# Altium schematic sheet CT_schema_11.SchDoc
size 274 x 160 mm
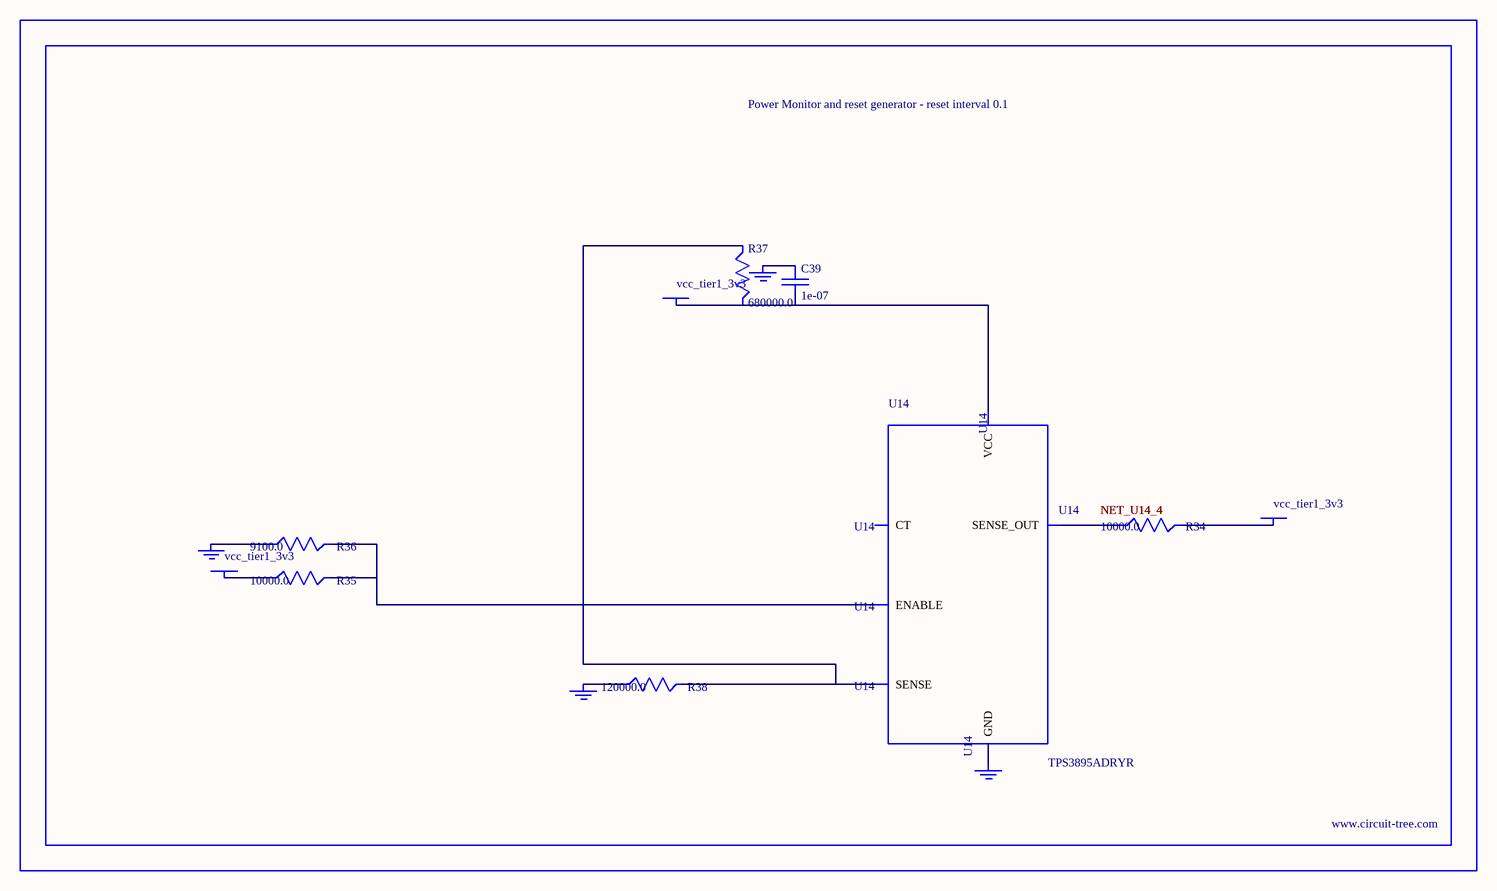
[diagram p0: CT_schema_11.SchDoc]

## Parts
BORDER10  (no value)
C39  1e-07  [C0402]
GND_INSTANCE_10_0  (no value)
GND_INSTANCE_10_1  (no value)
GND_INSTANCE_10_2  (no value)
GND_INSTANCE_10_3  (no value)
POWER_INSTANCE_10_0  vcc_tier1_3v3
POWER_INSTANCE_10_1  vcc_tier1_3v3
POWER_INSTANCE_10_2  vcc_tier1_3v3
R34  10000.0  [R0603]
R35  10000.0  [R0603]
R36  9100.0  [R0603]
R37  680000.0  [R0603]
R38  120000.0  [R0603]
U14  TPS3895ADRYR  [SON-6]

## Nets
NetC39_1: C39.1 GND_INSTANCE_10_2.0(GND)
NetC39_2: C39.2 POWER_INSTANCE_10_2.0(PWR) R37.2 U14.6(VCC)
NetGND_INSTANCE_10_0_0: GND_INSTANCE_10_0.0(GND) R36.1
NetGND_INSTANCE_10_1_0: GND_INSTANCE_10_1.0(GND) R38.1
NetGND_INSTANCE_10_3_0: GND_INSTANCE_10_3.0(GND) U14.2(GND)
NetPOWER_INSTANCE_10_0_0: POWER_INSTANCE_10_0.0(PWR) R35.1
NetPOWER_INSTANCE_10_1_0: POWER_INSTANCE_10_1.0(PWR) R34.2
NetR34_1: R34.1 U14.4(SENSE_OUT)
NetR35_2: R35.2 R36.2 U14.1(ENABLE)
NetR37_1: R37.1 R38.2 U14.3(SENSE)

Not connected (* = marked no-connect by the designer): U14 5(CT)

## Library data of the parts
BORDER10 = BORDER_PAGE10
C39 = C0402C104K3RACTU
GND_INSTANCE_10_0-GND_INSTANCE_10_3 = GND
POWER_INSTANCE_10_0-POWER_INSTANCE_10_2 = PWR
R34 R35 = RC0603JR-0710KL
R36 = RC0603JR-079K1L
R37 = RC0603JR-07680KL
R38 = RC0603JR-07120KL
